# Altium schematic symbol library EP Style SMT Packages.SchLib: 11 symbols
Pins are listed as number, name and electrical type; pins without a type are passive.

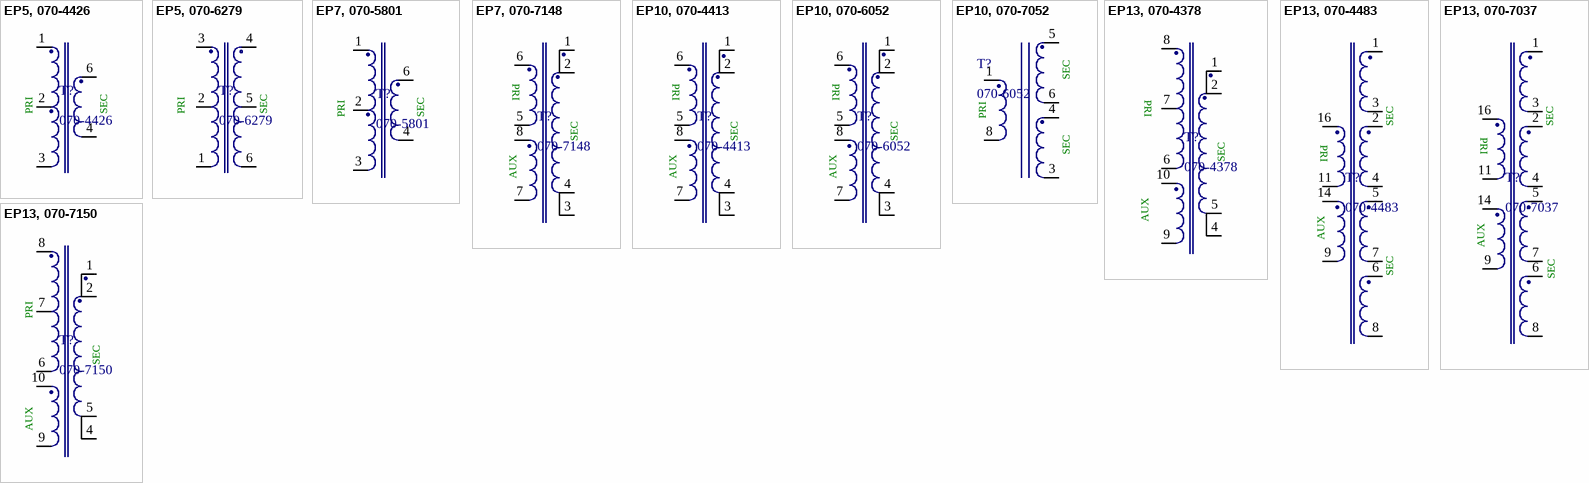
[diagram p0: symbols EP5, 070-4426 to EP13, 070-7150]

## EP5, 070-4426
designator T?, comment 070-4426
Transformer 6-Terminal, SMD, Horizontal, EP Style Bobbins, EP5; Manufacturer: Würth Elektronik Midcom; Core: Power: 150-1219, Digital: 150-1306
footprint EP5_4426 (SOP, 6-Leads, Body 6.60x8.26mm, Pitch 1.85mm, IPC Medium Density)
pins: 1, 2, 3, 4, 6

## EP5, 070-6279
designator T?, comment 070-6279
Transformer 6-Terminal, SMD, Horizontal, EP Style Bobbins, EP5; Manufacturer: Würth Elektronik Midcom; Core: Power: 150-1219, Digital: 150-1306
footprint EP5_6279 (SMD, 6-Leads, Body 7.00x9.10mm, Pitch 1.85mm, IPC Medium Density)
pins: 1, 2, 3, 4, 5, 6

## EP7, 070-5801
designator T?, comment 070-5801
Transformer 6-Terminal, SMD, Horizontal, EP Style Bobbins, EP7; Manufacturer: Würth Elektronik Midcom; Core: Power: 150-2365, Digital: 150-0341
footprint EP7_5801 (SMD, 6-Leads, Body 10.16x13.36mm, Pitch 2.50mm, IPC Medium Density)
pins: 1, 2, 3, 4, 6

## EP7, 070-7148
designator T?, comment 070-7148
EP7 8-Term., SMT, Horizontal; Manufacturer: Würth Elektronik Midcom; Core: Power: 150-2365, Digital: 150-0341
footprint EP7_7148 (SMD, 8-Leads, Body 9.78x9.14mm, Pitch 2.49mm, IPC Medium Density)
pins: 1, 2, 3, 4, 5, 6, 7, 8

## EP10, 070-4413
designator T?, comment 070-4413
EP10 8-Term., SMT, Horizontal (with shelves); Manufacturer: Würth Elektronik Midcom; Core: Power: 150-2361, Digital: 150-0339
footprint EP10_4413 (SMD, 8-Leads, Body 13.34x15.24mm, Pitch 2.49mm, IPC Medium Density)
pins: 1, 2, 3, 4, 5, 6, 7, 8

## EP10, 070-6052
designator T?, comment 070-6052
Transformer 8-Terminal, SMD, Horizontal, EP Style Bobbins, EP10; Manufacturer: Würth Elektronik Midcom; Core: Power: 150-2361, Digital: 150-0339
footprint EP10_6052 (SMD, 8-Leads, Body 13.34x15.24mm, Pitch 2.49mm, IPC Medium Density)
pins: 1, 2, 3, 4, 5, 6, 7, 8

## EP10, 070-7052
designator T?, comment 070-6052
Transformer 8-Terminal, SMD, Horizontal, EP Style Bobbins, EP10; Manufacturer: Würth Elektronik Midcom; Core: Power: 150-2361, Digital: 150-0339
footprint EP10_6052 (SMD, 8-Leads, Body 13.34x15.24mm, Pitch 2.49mm, IPC Medium Density)
footprint EP10_7052 (SMD, 8-Leads, Body 13.34x15.24mm, Pitch 2.49mm, IPC Medium Density)
pins: 1, 3, 4, 5, 6, 8

## EP13, 070-4378
designator T?, comment 070-4378
EP13 10-Term., SMT, Horizontal (with shelves); Manufacturer: Würth Elektronik Midcom; Core: Power: 150-2363, Digital: 150-0899
footprint EP13_4378 (SMD, 10-Leads, Body 13.46x17.75mm, Pitch 2.48mm, IPC Medium Density)
pins: 1, 2, 4, 5, 6, 7, 8, 9, 10

## EP13, 070-4483
designator T?, comment 070-4483
Transformer 12-Terminal, SMD, Horizontal, EP Style Bobbins, EP13; Manufacturer: Würth Elektronik Midcom; Core: 150-0899
footprint EP13_4483 (SOP, 16-Leads, Body 13.97x17.17mm, Pitch 1.70mm, IPC Medium Density)
pins: 1, 2, 3, 4, 5, 6, 7, 8, 9, 11, 14, 16

## EP13, 070-7037
designator T?, comment 070-7037
EP13 12-Term., SMT, Horizontal; Manufacturer: Würth Elektronik Midcom; Core: Power: 150-2363, Digital: 150-0899
footprint EP13_7037 (SMD, 16-Leads, Body 13.97x17.17mm, Pitch 1.70mm, IPC Medium Density)
pins: 1, 2, 3, 4, 5, 6, 7, 8, 9, 11, 14, 16

## EP13, 070-7150
designator T?, comment 070-7150
EP13 10-Term., SMT, Horizontal; Manufacturer: Würth Elektronik Midcom; Core: Power: 150-2363, Digital: 150-0899
footprint EP13_7150 (SMD, 10-Leads, Body 13.46x17.75mm, Pitch 2.50mm, IPC Medium Density)
pins: 1, 2, 4, 5, 6, 7, 8, 9, 10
